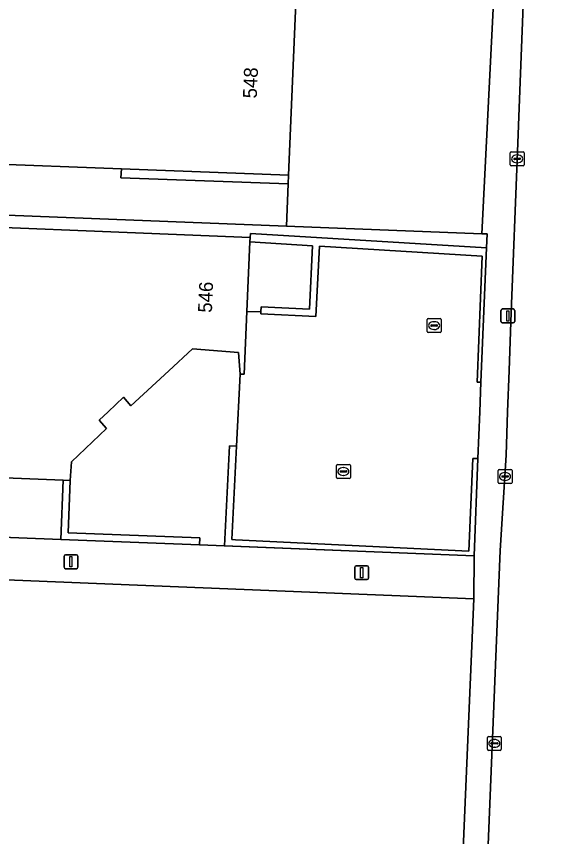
# Model space of a CAD drawing. Extents: x 161354 to 162026, y 386504 to 387460.
# Drawn here: x 161412.3 to 161450.3, y 386719.4 to 386778.4 of the extents above; entities that cross this region are included whole.
import ezdxf

# ---------------------------------------------------------------- set-up
doc = ezdxf.new("R2010")
doc.units = 0
for name, color, linetype in [('IMGEO_Erf', 7, 'Continuous'), ('IMGEO_Groenvoorziening', 7, 'Continuous'), ('IMGEO_Haag', 7, 'Continuous'), ('IMGEO_Kolk', 7, 'Continuous'), ('IMGEO_Lichtmast', 7, 'Continuous'), ('IMGEO_Pand', 7, 'Continuous'), ('IMGEO_Pand_nummerreeks', 7, 'Continuous'), ('IMGEO_Parkeervlak_open', 7, 'Continuous'), ('IMGEO_Rijbaan_lokaal_open', 7, 'Continuous'), ('IMGEO_Voetpad_open', 7, 'Continuous')]:
    doc.layers.add(name, color=color, linetype=linetype)

msp = doc.modelspace()

# ---------------------------------------------------------------- linework, layer by layer
at = {"layer": 'IMGEO_Erf'}
msp.add_lwpolyline([(161441.486, 386649.282), (161445.22, 386736.534), (161387.944, 386738.872), (161385.998, 386721.373), (161385.54, 386717.26), (161382.577, 386690.493), (161382.089, 386671.71), (161381.851, 386666.399), (161379.125, 386642.696)], dxfattribs=at)
at = {"layer": 'IMGEO_Groenvoorziening'}
for points in [[(161398.501, 386759.82), (161400.654, 386759.731), (161400.761, 386763.681), (161429.118, 386762.535), (161429.13, 386762.814), (161446.125, 386761.783), (161446.167, 386762.794), (161445.775, 386762.809), (161431.741, 386763.351), (161390.826, 386764.964), (161389.175, 386750), (161388.279, 386741.884), (161415.504, 386740.814), (161415.671, 386745.072), (161400.027, 386745.71), (161400.206, 386749.704), (161398.124, 386749.814), (161398.131, 386750)], [(161429.13, 386762.814), (161429.118, 386762.535), (161429.104, 386762.215), (161433.597, 386761.942), (161433.374, 386757.371), (161429.898, 386757.541), (161429.881, 386757.196), (161429.873, 386757.042), (161433.849, 386756.848), (161434.096, 386761.912), (161445.813, 386761.201), (161445.453, 386752.138), (161445.591, 386752.13), (161445.724, 386752.122), (161446.125, 386761.783)], [(161427.788, 386740.814), (161428.137, 386747.536), (161427.638, 386747.562), (161427.263, 386740.352), (161445.243, 386739.646), (161445.509, 386746.631), (161445.148, 386746.638), (161444.858, 386739.979), (161428.065, 386740.795)], [(161416.171, 386745.052), (161415.671, 386745.072), (161415.504, 386740.814), (161425.464, 386740.423), (161425.484, 386740.923), (161416.023, 386741.294)]]:
    msp.add_lwpolyline(points, close=True, dxfattribs=at)
at = {"layer": 'IMGEO_Haag'}
for points in [[(161429.13, 386762.814), (161429.118, 386762.535), (161429.104, 386762.215), (161433.597, 386761.942), (161433.374, 386757.371), (161429.898, 386757.541), (161429.881, 386757.196), (161429.873, 386757.042), (161433.849, 386756.848), (161434.096, 386761.912), (161445.813, 386761.201), (161445.453, 386752.138), (161445.591, 386752.13), (161445.724, 386752.122), (161446.125, 386761.783)], [(161445.509, 386746.631), (161445.148, 386746.638), (161444.858, 386739.979), (161428.065, 386740.795), (161427.788, 386740.814), (161428.137, 386747.536), (161427.638, 386747.562), (161427.244, 386740.353), (161445.243, 386739.646)], [(161416.023, 386741.294), (161416.171, 386745.052), (161415.671, 386745.072), (161415.504, 386740.814), (161425.464, 386740.423), (161425.484, 386740.923)]]:
    msp.add_lwpolyline(points, close=True, dxfattribs=at)
at = {"layer": 'IMGEO_Kolk'}
for p, q in [((161447.828, 386767.769), (161447.828, 386768.621)), ((161447.903, 386768.695), (161448.755, 386768.695)), ((161448.13, 386768.238), (161448.528, 386768.238)), ((161448.316, 386768.475), (161448.341, 386768.475)), ((161448.829, 386768.621), (161448.829, 386767.769)), ((161448.755, 386767.695), (161447.903, 386767.695)), ((161448.087, 386768.189), (161448.087, 386768.201)), ((161448.525, 386768.152), (161448.127, 386768.152)), ((161448.339, 386767.915), (161448.314, 386767.915)), ((161448.571, 386768.201), (161448.571, 386768.189)), ((161441.853, 386755.776), (161441.853, 386756.628)), ((161441.928, 386756.702), (161442.78, 386756.702)), ((161442.341, 386756.482), (161442.366, 386756.482)), ((161442.854, 386756.628), (161442.854, 386755.776)), ((161442.112, 386756.196), (161442.112, 386756.208)), ((161442.55, 386756.159), (161442.152, 386756.159)), ((161442.155, 386756.245), (161442.553, 386756.245)), ((161442.364, 386755.922), (161442.339, 386755.922)), ((161442.596, 386756.208), (161442.596, 386756.196)), ((161442.78, 386755.702), (161441.928, 386755.702)), ((161435.323, 386745.281), (161435.323, 386746.133)), ((161435.398, 386746.207), (161436.25, 386746.207)), ((161435.811, 386745.987), (161435.836, 386745.987)), ((161436.324, 386746.133), (161436.324, 386745.281)), ((161447.031, 386745.845), (161447.883, 386745.845)), ((161435.582, 386745.701), (161435.582, 386745.713)), ((161436.02, 386745.664), (161435.622, 386745.664)), ((161435.625, 386745.75), (161436.023, 386745.75)), ((161435.834, 386745.427), (161435.809, 386745.427)), ((161436.066, 386745.713), (161436.066, 386745.701)), ((161446.956, 386744.919), (161446.956, 386745.771)), ((161447.215, 386745.339), (161447.215, 386745.351)), ((161447.653, 386745.302), (161447.255, 386745.302)), ((161447.258, 386745.388), (161447.656, 386745.388)), ((161447.444, 386745.625), (161447.469, 386745.625)), ((161447.699, 386745.351), (161447.699, 386745.339)), ((161447.957, 386745.771), (161447.957, 386744.919)), ((161436.25, 386745.207), (161435.398, 386745.207)), ((161447.883, 386744.845), (161447.031, 386744.845)), ((161447.467, 386745.065), (161447.442, 386745.065)), ((161446.184, 386725.72), (161446.184, 386726.572)), ((161446.259, 386726.646), (161447.111, 386726.646)), ((161446.672, 386726.426), (161446.697, 386726.426)), ((161447.185, 386726.572), (161447.185, 386725.72)), ((161446.443, 386726.14), (161446.443, 386726.152)), ((161446.881, 386726.103), (161446.483, 386726.103)), ((161446.486, 386726.189), (161446.884, 386726.189)), ((161446.695, 386725.866), (161446.67, 386725.866)), ((161446.927, 386726.152), (161446.927, 386726.14)), ((161447.111, 386725.646), (161446.259, 386725.646))]:
    msp.add_line(p, q, dxfattribs=at)
for points in [[(161447.828, 386767.769), (161447.828, 386768.621)], [(161447.903, 386768.695), (161448.755, 386768.695)], [(161448.829, 386768.621), (161448.829, 386767.769)], [(161448.755, 386767.695), (161447.903, 386767.695)], [(161441.853, 386755.776), (161441.853, 386756.628)], [(161441.928, 386756.702), (161442.78, 386756.702)], [(161442.854, 386756.628), (161442.854, 386755.776)], [(161442.78, 386755.702), (161441.928, 386755.702)], [(161435.323, 386745.281), (161435.323, 386746.133)], [(161435.398, 386746.207), (161436.25, 386746.207)], [(161436.324, 386746.133), (161436.324, 386745.281)], [(161447.031, 386745.845), (161447.883, 386745.845)], [(161446.956, 386744.919), (161446.956, 386745.771)], [(161447.957, 386745.771), (161447.957, 386744.919)], [(161436.25, 386745.207), (161435.398, 386745.207)], [(161447.883, 386744.845), (161447.031, 386744.845)], [(161446.184, 386725.72), (161446.184, 386726.572)], [(161446.259, 386726.646), (161447.111, 386726.646)], [(161447.185, 386726.572), (161447.185, 386725.72)], [(161447.111, 386725.646), (161446.259, 386725.646)]]:
    msp.add_lwpolyline(points, dxfattribs=at)
for centre, radius, start, end in [((161447.905, 386768.619), 0.0765, 91.55205, 178.44795), ((161447.905, 386768.619), 0.0765, 91.55205, 178.44795), ((161448.127, 386768.198), 0.0403, 85.87752, 175.75265), ((161448.532, 386768.2), 0.0386, 1.73085, 96.63898), ((161448.753, 386768.619), 0.0765, 1.55205, 88.44795), ((161448.753, 386768.619), 0.0765, 1.55205, 88.44795), ((161447.905, 386767.771), 0.0765, 181.55205, 268.44795), ((161447.905, 386767.771), 0.0765, 181.55205, 268.44795), ((161448.124, 386768.188), 0.0366, 178.93798, 274.71019), ((161448.528, 386768.195), 0.043, 264.86636, 352.45326), ((161448.753, 386767.771), 0.0765, 271.55205, 358.44795), ((161448.753, 386767.771), 0.0765, 271.55205, 358.44795), ((161441.93, 386756.626), 0.0765, 91.55205, 178.44795), ((161441.93, 386756.626), 0.0765, 91.55205, 178.44795), ((161442.778, 386756.626), 0.0765, 1.55205, 88.44795), ((161442.778, 386756.626), 0.0765, 1.55205, 88.44795), ((161442.152, 386756.205), 0.0403, 85.87752, 175.75265), ((161442.149, 386756.195), 0.0366, 178.93798, 274.71019), ((161442.553, 386756.202), 0.043, 264.86636, 352.45326), ((161442.557, 386756.207), 0.0386, 1.73085, 96.63898), ((161441.93, 386755.778), 0.0765, 181.55205, 268.44795), ((161441.93, 386755.778), 0.0765, 181.55205, 268.44795), ((161442.778, 386755.778), 0.0765, 271.55205, 358.44795), ((161442.778, 386755.778), 0.0765, 271.55205, 358.44795), ((161435.4, 386746.131), 0.0765, 91.55205, 178.44795), ((161435.4, 386746.131), 0.0765, 91.55205, 178.44795), ((161436.248, 386746.131), 0.0765, 1.55205, 88.44795), ((161436.248, 386746.131), 0.0765, 1.55205, 88.44795), ((161447.033, 386745.769), 0.0765, 91.55205, 178.44795), ((161447.033, 386745.769), 0.0765, 91.55205, 178.44795), ((161447.881, 386745.769), 0.0765, 1.55205, 88.44795), ((161447.881, 386745.769), 0.0765, 1.55205, 88.44795), ((161435.4, 386745.283), 0.0765, 181.55205, 268.44795), ((161435.4, 386745.283), 0.0765, 181.55205, 268.44795), ((161435.622, 386745.71), 0.0403, 85.87752, 175.75265), ((161435.619, 386745.7), 0.0366, 178.93798, 274.71019), ((161436.023, 386745.707), 0.043, 264.86636, 352.45326), ((161436.027, 386745.712), 0.0386, 1.73085, 96.63898), ((161436.248, 386745.283), 0.0765, 271.55205, 358.44795), ((161436.248, 386745.283), 0.0765, 271.55205, 358.44795), ((161447.255, 386745.348), 0.0403, 85.87752, 175.75265), ((161447.252, 386745.338), 0.0366, 178.93798, 274.71019), ((161447.656, 386745.345), 0.043, 264.86636, 352.45326), ((161447.66, 386745.35), 0.0386, 1.73085, 96.63898), ((161447.033, 386744.921), 0.0765, 181.55205, 268.44795), ((161447.033, 386744.921), 0.0765, 181.55205, 268.44795), ((161447.881, 386744.921), 0.0765, 271.55205, 358.44795), ((161447.881, 386744.921), 0.0765, 271.55205, 358.44795), ((161446.261, 386726.57), 0.0765, 91.55205, 178.44795), ((161446.261, 386726.57), 0.0765, 91.55205, 178.44795), ((161447.109, 386726.57), 0.0765, 1.55205, 88.44795), ((161447.109, 386726.57), 0.0765, 1.55205, 88.44795), ((161446.483, 386726.149), 0.0403, 85.87752, 175.75265), ((161446.48, 386726.139), 0.0366, 178.93798, 274.71019), ((161446.884, 386726.146), 0.043, 264.86636, 352.45326), ((161446.888, 386726.151), 0.0386, 1.73085, 96.63898), ((161446.261, 386725.722), 0.0765, 181.55205, 268.44795), ((161446.261, 386725.722), 0.0765, 181.55205, 268.44795), ((161447.109, 386725.722), 0.0765, 271.55205, 358.44795), ((161447.109, 386725.722), 0.0765, 271.55205, 358.44795)]:
    msp.add_arc(centre, radius, start, end, dxfattribs=at)
for centre, major_axis, ratio, start_param, end_param in [((161448.315, 386768.195), (-0.387, 0.002), 0.722429, 4.712389, 7.853982), ((161448.34, 386768.195), (-0.39, 0.002), 0.717154, 1.570796, 4.712389), ((161442.34, 386756.202), (-0.387, 0.002), 0.722429, 4.712389, 7.853982), ((161442.365, 386756.202), (-0.39, 0.002), 0.717154, 1.570796, 4.712389), ((161435.81, 386745.707), (-0.387, 0.002), 0.722429, 4.712389, 7.853982), ((161435.835, 386745.707), (-0.39, 0.002), 0.717154, 1.570796, 4.712389), ((161447.443, 386745.345), (-0.387, 0.002), 0.722429, 4.712389, 7.853982), ((161447.468, 386745.345), (-0.39, 0.002), 0.717154, 1.570796, 4.712389), ((161446.671, 386726.146), (-0.387, 0.002), 0.722429, 4.712389, 7.853982), ((161446.696, 386726.146), (-0.39, 0.002), 0.717154, 1.570796, 4.712389)]:
    msp.add_ellipse(centre, major_axis=major_axis, ratio=ratio, start_param=start_param, end_param=end_param, dxfattribs=at)
at = {"layer": 'IMGEO_Lichtmast'}
for p, q in [((161447.16, 386756.496), (161447.16, 386757.296)), ((161447.16, 386757.296), (161447.16, 386756.496)), ((161447.26, 386757.396), (161448.05, 386757.396)), ((161448.05, 386757.396), (161447.26, 386757.396)), ((161448.15, 386757.296), (161448.15, 386756.496)), ((161448.15, 386756.496), (161448.15, 386757.296)), ((161448.05, 386756.396), (161447.26, 386756.396)), ((161447.26, 386756.396), (161448.05, 386756.396)), ((161415.723, 386738.813), (161415.723, 386739.613)), ((161415.723, 386739.613), (161415.723, 386738.813)), ((161415.823, 386739.713), (161416.613, 386739.713)), ((161416.613, 386739.713), (161415.823, 386739.713)), ((161416.713, 386739.613), (161416.713, 386738.813)), ((161416.713, 386738.813), (161416.713, 386739.613)), ((161436.645, 386738.03), (161436.645, 386738.83)), ((161436.645, 386738.83), (161436.645, 386738.03)), ((161436.745, 386738.93), (161437.535, 386738.93)), ((161437.535, 386738.93), (161436.745, 386738.93)), ((161437.635, 386738.83), (161437.635, 386738.03)), ((161437.635, 386738.03), (161437.635, 386738.83)), ((161416.613, 386738.713), (161415.823, 386738.713)), ((161415.823, 386738.713), (161416.613, 386738.713)), ((161437.535, 386737.93), (161436.745, 386737.93)), ((161436.745, 386737.93), (161437.535, 386737.93))]:
    msp.add_line(p, q, dxfattribs=at)
for points in [[(161447.58, 386757.271), (161447.73, 386757.271), (161447.73, 386756.521), (161447.58, 386756.521), (161447.58, 386757.271)], [(161416.143, 386739.588), (161416.293, 386739.588), (161416.293, 386738.838), (161416.143, 386738.838), (161416.143, 386739.588)], [(161437.065, 386738.805), (161437.215, 386738.805), (161437.215, 386738.055), (161437.065, 386738.055), (161437.065, 386738.805)]]:
    msp.add_lwpolyline(points, dxfattribs=at)
for centre, start, end in [((161447.26, 386757.296), 90, 180), ((161447.26, 386757.296), 90, 180), ((161448.05, 386757.296), 0, 90), ((161448.05, 386757.296), 360, 90), ((161447.26, 386756.496), 180, 270), ((161447.26, 386756.496), 180, 270), ((161448.05, 386756.496), 270, 0), ((161448.05, 386756.496), 270, 0), ((161415.823, 386739.613), 90, 180), ((161415.823, 386739.613), 90, 180), ((161416.613, 386739.613), 0, 90), ((161416.613, 386739.613), 360, 90), ((161415.823, 386738.813), 180, 270), ((161415.823, 386738.813), 180, 270), ((161416.613, 386738.813), 270, 0), ((161416.613, 386738.813), 270, 0), ((161436.745, 386738.83), 90, 180), ((161436.745, 386738.83), 90, 180), ((161437.535, 386738.83), 0, 90), ((161437.535, 386738.83), 360, 90), ((161436.745, 386738.03), 180, 270), ((161436.745, 386738.03), 180, 270), ((161437.535, 386738.03), 270, 0), ((161437.535, 386738.03), 270, 0)]:
    msp.add_arc(centre, 0.1, start, end, dxfattribs=at)
at = {"layer": 'IMGEO_Pand'}
for points in [[(161432.449, 386780.581), (161427.921, 386780.759), (161404.241, 386781.689), (161404.072, 386777.16), (161403.996, 386775.14), (161400.1, 386775.238), (161399.751, 386766.654), (161409.697, 386766.272), (161409.747, 386767.862), (161419.859, 386767.475), (161431.881, 386767.014)], [(161424.972, 386754.523), (161428.28, 386754.255), (161428.407, 386752.716), (161428.685, 386752.707), (161428.884, 386757.213), (161429.104, 386762.215), (161429.118, 386762.535), (161400.761, 386763.681), (161400.654, 386759.731), (161398.501, 386759.82), (161398.131, 386750), (161398.124, 386749.814), (161400.206, 386749.704), (161400.027, 386745.71), (161415.671, 386745.072), (161416.171, 386745.052), (161416.263, 386746.399), (161418.782, 386748.796), (161418.258, 386749.386), (161418.899, 386750), (161419.996, 386751.05), (161420.535, 386750.432), (161423.257, 386752.942)]]:
    msp.add_lwpolyline(points, close=True, dxfattribs=at)
at = {"layer": 'IMGEO_Parkeervlak_open'}
for points in [[(161446.64, 386779.978), (161432.449, 386780.581), (161431.881, 386767.014), (161431.844, 386766.388), (161431.741, 386763.351), (161445.775, 386762.809)], [(161445.724, 386752.122), (161445.591, 386752.13), (161445.453, 386752.138), (161445.813, 386761.201), (161434.096, 386761.912), (161433.849, 386756.848), (161429.873, 386757.042), (161429.881, 386757.196), (161428.884, 386757.213), (161428.685, 386752.707), (161428.407, 386752.716), (161428.137, 386747.536), (161427.788, 386740.814), (161428.065, 386740.795), (161444.858, 386739.979), (161445.148, 386746.638), (161445.509, 386746.631), (161445.641, 386750)]]:
    msp.add_lwpolyline(points, close=True, dxfattribs=at)
at = {"layer": 'IMGEO_Rijbaan_lokaal_open'}
msp.add_lwpolyline([(161450.094, 386812.939), (161449.685, 386804.169), (161449.505, 386798.966), (161449.271, 386792.965), (161449.164, 386789.722), (161448.49, 386772.488), (161448.343, 386768.709), (161447.891, 386757.154), (161447.745, 386752.965), (161447.642, 386750), (161447.533, 386746.883), (161447.104, 386740.028), (161445.57, 386702.409), (161444.737, 386682.723), (161451.804, 386682.432), (161452.536, 386699.819), (161454.613, 386749.99), (161455.644, 386778.834)], dxfattribs=at)
at = {"layer": 'IMGEO_Voetpad_open'}
for points in [[(161447.104, 386740.028), (161447.533, 386746.883), (161447.642, 386750), (161447.745, 386752.965), (161447.891, 386757.154), (161448.343, 386768.709), (161448.49, 386772.488), (161449.164, 386789.722), (161449.271, 386792.965), (161449.505, 386798.966), (161449.685, 386804.169), (161450.094, 386812.939), (161447.06, 386813.654)], [(161448.152, 386810.848), (161446.875, 386779.968), (161446.64, 386779.978), (161445.775, 386762.809), (161446.167, 386762.794), (161446.125, 386761.783), (161445.724, 386752.122), (161445.641, 386750), (161445.509, 386746.631), (161445.243, 386739.646), (161445.22, 386736.534), (161441.486, 386649.282), (161439.468, 386649.379), (161439.242, 386644.412), (161443.358, 386644.313), (161444.618, 386679.833), (161444.737, 386682.723), (161445.57, 386702.409), (161447.104, 386740.028)]]:
    msp.add_lwpolyline(points, dxfattribs=at)
for points in [[(161390.826, 386764.964), (161431.741, 386763.351), (161431.844, 386766.388), (161419.809, 386766.821), (161419.859, 386767.475), (161409.747, 386767.862), (161409.697, 386766.272), (161399.751, 386766.654), (161400.1, 386775.238), (161403.996, 386775.14), (161404.072, 386777.16), (161398.176, 386777.414), (161397.87, 386769.993), (161397.692, 386765.691), (161393.203, 386765.85), (161390.933, 386765.929)], [(161431.881, 386767.014), (161419.859, 386767.475), (161419.809, 386766.821), (161431.844, 386766.388)], [(161433.597, 386761.942), (161429.104, 386762.215), (161428.884, 386757.213), (161429.881, 386757.196), (161429.898, 386757.541), (161433.374, 386757.371)], [(161428.28, 386754.255), (161424.972, 386754.523), (161423.257, 386752.942), (161420.535, 386750.432), (161419.996, 386751.05), (161418.899, 386750), (161418.258, 386749.386), (161418.782, 386748.796), (161416.263, 386746.399), (161416.171, 386745.052), (161416.023, 386741.294), (161425.484, 386740.923), (161425.464, 386740.423), (161427.263, 386740.352), (161427.638, 386747.562), (161428.137, 386747.536), (161428.407, 386752.716)], [(161427.263, 386740.352), (161425.464, 386740.423), (161415.504, 386740.814), (161388.279, 386741.884), (161387.944, 386738.872), (161445.22, 386736.534), (161445.243, 386739.646)]]:
    msp.add_lwpolyline(points, close=True, dxfattribs=at)

# ---------------------------------------------------------------- texts
at = {"layer": 'IMGEO_Pand_nummerreeks'}
for s, rotation, p in [('548', 87.60525, (161429.59, 386772.529)), ('546', 87.4792, (161426.357, 386757.11))]:
    msp.add_text(s, height=1, rotation=rotation, dxfattribs=at).set_placement(p)

doc.saveas('drawing.dxf')
